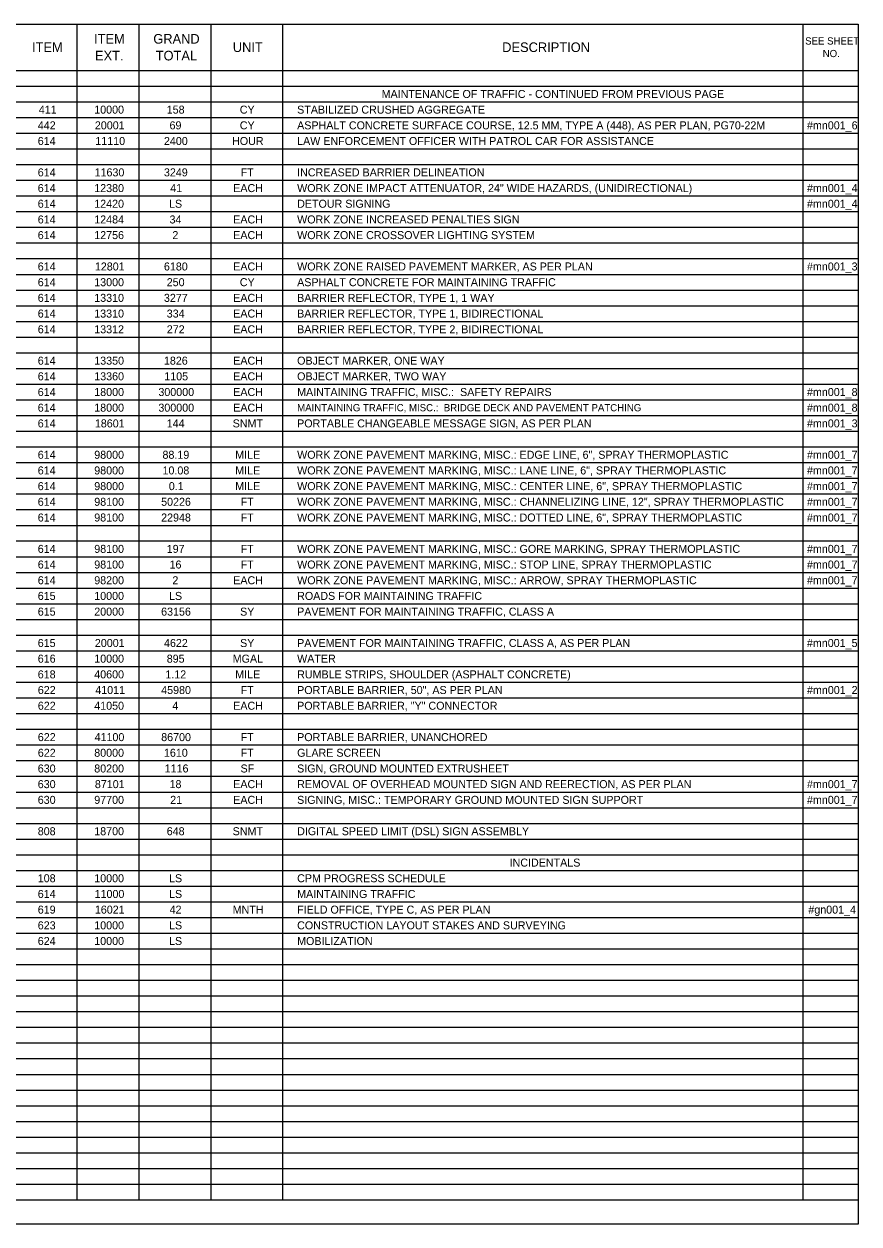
# Model space of a CAD drawing. Extents: x -542 to 295, y -281 to 32.
# Drawn here: x -400.45 to -385.84, y -160.59 to -139.59 of the extents above; entities that cross this region are included whole.
import ezdxf

# ---------------------------------------------------------------- set-up
doc = ezdxf.new("R2010")
doc.units = 0
for name, color, linetype in [('SC_Scratch1', 7, 'Continuous'), ('SH_Data', 7, 'Continuous'), ('SH_Text', 7, 'Continuous')]:
    doc.layers.add(name, color=color, linetype=linetype)

msp = doc.modelspace()

# ---------------------------------------------------------------- linework, layer by layer
at = {"layer": 'SC_Scratch1'}
msp.add_lwpolyline([(-416.359, -139.593), (-385.859, -139.593), (-385.859, -160.593), (-416.359, -160.593)], close=True, dxfattribs=at)
at = {"layer": 'SH_Data'}
for p, q in [((-416.359, -139.593), (-385.859, -139.593)), ((-399.523, -139.593), (-399.523, -160.17)), ((-398.437, -139.593), (-398.437, -160.17)), ((-397.182, -139.593), (-397.182, -160.17)), ((-395.926, -139.593), (-395.926, -160.17)), ((-386.827, -139.593), (-386.827, -160.17)), ((-385.859, -139.593), (-385.859, -160.17)), ((-416.359, -140.405), (-385.859, -140.405)), ((-416.359, -140.68), (-385.859, -140.68)), ((-416.359, -140.954), (-385.859, -140.954)), ((-416.359, -141.229), (-385.859, -141.229)), ((-416.359, -141.503), (-385.859, -141.503)), ((-416.359, -141.778), (-385.859, -141.778)), ((-416.359, -142.052), (-385.859, -142.052)), ((-416.359, -142.327), (-385.859, -142.327)), ((-416.359, -142.601), (-385.859, -142.601)), ((-416.359, -142.876), (-385.859, -142.876)), ((-416.359, -143.15), (-385.859, -143.15)), ((-416.359, -143.425), (-385.859, -143.425)), ((-416.359, -143.699), (-385.859, -143.699)), ((-416.359, -143.974), (-385.859, -143.974)), ((-416.359, -144.248), (-385.859, -144.248)), ((-416.359, -144.523), (-385.859, -144.523)), ((-416.359, -144.797), (-385.859, -144.797)), ((-416.359, -145.072), (-385.859, -145.072)), ((-416.359, -145.346), (-385.859, -145.346)), ((-416.359, -145.621), (-385.859, -145.621)), ((-416.359, -145.895), (-385.859, -145.895)), ((-416.359, -146.17), (-385.859, -146.17)), ((-416.359, -146.444), (-385.859, -146.444)), ((-416.359, -146.719), (-385.859, -146.719)), ((-416.359, -146.993), (-385.859, -146.993)), ((-416.359, -147.268), (-385.859, -147.268)), ((-416.359, -147.542), (-385.859, -147.542)), ((-416.359, -147.817), (-385.859, -147.817)), ((-416.359, -148.091), (-385.859, -148.091)), ((-416.359, -148.366), (-385.859, -148.366)), ((-416.359, -148.64), (-385.859, -148.64)), ((-416.359, -148.915), (-385.859, -148.915)), ((-416.359, -149.189), (-385.859, -149.189)), ((-416.359, -149.464), (-385.859, -149.464)), ((-416.359, -149.738), (-385.859, -149.738)), ((-416.359, -150.013), (-385.859, -150.013)), ((-416.359, -150.287), (-385.859, -150.287)), ((-416.359, -150.562), (-385.859, -150.562)), ((-416.359, -150.836), (-385.859, -150.836)), ((-416.359, -151.111), (-385.859, -151.111)), ((-416.359, -151.385), (-385.859, -151.385)), ((-416.359, -151.66), (-385.859, -151.66)), ((-416.359, -151.935), (-385.859, -151.935)), ((-416.359, -152.209), (-385.859, -152.209)), ((-416.359, -152.484), (-385.859, -152.484)), ((-416.359, -152.758), (-385.859, -152.758)), ((-416.359, -153.033), (-385.859, -153.033)), ((-416.359, -153.307), (-385.859, -153.307)), ((-416.359, -153.582), (-385.859, -153.582)), ((-416.359, -153.856), (-385.859, -153.856)), ((-416.359, -154.131), (-385.859, -154.131)), ((-416.359, -154.405), (-385.859, -154.405)), ((-416.359, -154.68), (-385.859, -154.68)), ((-416.359, -154.68), (-385.859, -154.68)), ((-416.359, -154.954), (-385.859, -154.954)), ((-416.359, -155.229), (-385.859, -155.229)), ((-416.359, -155.503), (-385.859, -155.503)), ((-416.359, -155.778), (-385.859, -155.778)), ((-416.359, -156.052), (-385.859, -156.052)), ((-416.359, -156.327), (-385.859, -156.327)), ((-416.359, -156.601), (-385.859, -156.601)), ((-416.359, -156.876), (-385.859, -156.876)), ((-416.359, -157.15), (-385.859, -157.15)), ((-416.359, -157.425), (-385.859, -157.425)), ((-416.359, -157.699), (-385.859, -157.699)), ((-416.359, -157.974), (-385.859, -157.974)), ((-416.359, -158.248), (-385.859, -158.248)), ((-416.359, -158.523), (-385.859, -158.523)), ((-416.359, -158.797), (-385.859, -158.797)), ((-416.359, -159.072), (-385.859, -159.072)), ((-416.359, -159.346), (-385.859, -159.346)), ((-416.359, -159.621), (-385.859, -159.621)), ((-416.359, -159.895), (-385.859, -159.895)), ((-416.359, -160.17), (-385.859, -160.17))]:
    msp.add_line(p, q, dxfattribs=at)

# ---------------------------------------------------------------- texts
at = {"layer": 'SH_Text'}
for s, height, p in [('ITEM', 0.168, (-399.222, -139.936)), ('GRAND ', 0.168, (-398.186, -139.936)), ('SEE SHEET ', 0.126, (-386.784, -139.952)), ('ITEM', 0.168, (-400.307, -140.083)), ('EXT.', 0.168, (-399.205, -140.23)), ('TOTAL', 0.168, (-398.144, -140.23)), ('UNIT', 0.168, (-396.795, -140.083)), ('DESCRIPTION', 0.168, (-392.083, -140.083)), ('NO.', 0.126, (-386.477, -140.172)), ('MAINTENANCE OF TRAFFIC - CONTINUED FROM PREVIOUS PAGE', 0.14, (-394.192, -140.887)), ('411', 0.14, (-400.189, -141.161)), ('10000', 0.14, (-399.219, -141.161)), ('158', 0.14, (-397.951, -141.161)), ('CY', 0.14, (-396.673, -141.161)), ('STABILIZED CRUSHED AGGREGATE', 0.14, (-395.67, -141.161)), ('442', 0.14, (-400.206, -141.436)), ('20001', 0.14, (-399.208, -141.436)), ('69', 0.14, (-397.902, -141.436)), ('CY', 0.14, (-396.673, -141.436)), ('ASPHALT CONCRETE SURFACE COURSE, 12.5 MM, TYPE A (448), AS PER PLAN, PG70-22M', 0.14, (-395.67, -141.436)), ('#mn001_6', 0.14, (-386.752, -141.436)), ('614', 0.14, (-400.207, -141.71)), ('11110', 0.14, (-399.2, -141.71)), ('2400', 0.14, (-398, -141.71)), ('HOUR', 0.14, (-396.808, -141.71)), ('LAW ENFORCEMENT OFFICER WITH PATROL CAR FOR ASSISTANCE', 0.14, (-395.67, -141.71)), ('614', 0.14, (-400.207, -142.259)), ('11630', 0.14, (-399.213, -142.259)), ('3249', 0.14, (-398, -142.259)), ('FT', 0.14, (-396.658, -142.259)), ('INCREASED BARRIER DELINEATION', 0.14, (-395.67, -142.259)), ('614', 0.14, (-400.207, -142.534)), ('12380', 0.14, (-399.219, -142.534)), ('41', 0.14, (-397.89, -142.534)), ('EACH', 0.14, (-396.788, -142.534)), ('WORK ZONE IMPACT ATTENUATOR, 24" WIDE HAZARDS, (UNIDIRECTIONAL)', 0.14, (-395.67, -142.534)), ('#mn001_4', 0.14, (-386.752, -142.534)), ('614', 0.14, (-400.207, -142.808)), ('12420', 0.14, (-399.219, -142.808)), ('LS', 0.14, (-397.911, -142.808)), ('DETOUR SIGNING', 0.14, (-395.67, -142.808)), ('#mn001_4', 0.14, (-386.752, -142.808)), ('614', 0.14, (-400.207, -143.083)), ('12484', 0.14, (-399.219, -143.083)), ('34', 0.14, (-397.902, -143.083)), ('EACH', 0.14, (-396.788, -143.083)), ('WORK ZONE INCREASED PENALTIES SIGN', 0.14, (-395.67, -143.083)), ('614', 0.14, (-400.207, -143.357)), ('12756', 0.14, (-399.219, -143.357)), ('2', 0.14, (-397.852, -143.357)), ('EACH', 0.14, (-396.788, -143.357)), ('WORK ZONE CROSSOVER LIGHTING SYSTEM', 0.14, (-395.67, -143.357)), ('614', 0.14, (-400.207, -143.906)), ('12801', 0.14, (-399.208, -143.906)), ('6180', 0.14, (-398, -143.906)), ('EACH', 0.14, (-396.788, -143.906)), ('WORK ZONE RAISED PAVEMENT MARKER, AS PER PLAN', 0.14, (-395.67, -143.906)), ('#mn001_3', 0.14, (-386.752, -143.906)), ('614', 0.14, (-400.207, -144.181)), ('13000', 0.14, (-399.219, -144.181)), ('250', 0.14, (-397.951, -144.181)), ('CY', 0.14, (-396.673, -144.181)), ('ASPHALT CONCRETE FOR MAINTAINING TRAFFIC', 0.14, (-395.67, -144.181)), ('614', 0.14, (-400.207, -144.455)), ('13310', 0.14, (-399.219, -144.455)), ('3277', 0.14, (-398, -144.455)), ('EACH', 0.14, (-396.788, -144.455)), ('BARRIER REFLECTOR, TYPE 1, 1 WAY', 0.14, (-395.67, -144.455)), ('614', 0.14, (-400.207, -144.73)), ('13310', 0.14, (-399.219, -144.73)), ('334', 0.14, (-397.951, -144.73)), ('EACH', 0.14, (-396.788, -144.73)), ('BARRIER REFLECTOR, TYPE 1, BIDIRECTIONAL', 0.14, (-395.67, -144.73)), ('614', 0.14, (-400.207, -145.005)), ('13312', 0.14, (-399.219, -145.005)), ('272', 0.14, (-397.95, -145.005)), ('EACH', 0.14, (-396.788, -145.005)), ('BARRIER REFLECTOR, TYPE 2, BIDIRECTIONAL', 0.14, (-395.67, -145.005)), ('614', 0.14, (-400.207, -145.554)), ('13350', 0.14, (-399.219, -145.554)), ('1826', 0.14, (-398, -145.554)), ('EACH', 0.14, (-396.788, -145.554)), ('OBJECT MARKER, ONE WAY', 0.14, (-395.67, -145.554)), ('614', 0.14, (-400.207, -145.828)), ('13360', 0.14, (-399.219, -145.828)), ('1105', 0.14, (-397.994, -145.828)), ('EACH', 0.14, (-396.788, -145.828)), ('OBJECT MARKER, TWO WAY', 0.14, (-395.67, -145.828)), ('614', 0.14, (-400.207, -146.103)), ('18000', 0.14, (-399.219, -146.103)), ('300000', 0.14, (-398.097, -146.103)), ('EACH', 0.14, (-396.788, -146.103)), ('MAINTAINING TRAFFIC, MISC.:  SAFETY REPAIRS', 0.14, (-395.67, -146.103)), ('#mn001_8', 0.14, (-386.752, -146.103)), ('614', 0.14, (-400.207, -146.377)), ('18000', 0.14, (-399.219, -146.377)), ('300000', 0.14, (-398.097, -146.377)), ('EACH', 0.14, (-396.788, -146.377)), ('MAINTAINING TRAFFIC, MISC.:  BRIDGE DECK AND PAVEMENT PATCHING', 0.126, (-395.67, -146.37)), ('#mn001_8', 0.14, (-386.752, -146.377)), ('614', 0.14, (-400.207, -146.652)), ('18601', 0.14, (-399.208, -146.652)), ('144', 0.14, (-397.951, -146.652)), ('SNMT', 0.14, (-396.798, -146.652)), ('PORTABLE CHANGEABLE MESSAGE SIGN, AS PER PLAN', 0.14, (-395.67, -146.652)), ('#mn001_3', 0.14, (-386.752, -146.652)), ('614', 0.14, (-400.207, -147.201)), ('98000', 0.14, (-399.219, -147.201)), ('88.19', 0.14, (-398.025, -147.201)), ('MILE', 0.14, (-396.753, -147.201)), ('WORK ZONE PAVEMENT MARKING, MISC.: EDGE LINE, 6", SPRAY THERMOPLASTIC', 0.14, (-395.67, -147.201)), ('#mn001_7', 0.14, (-386.752, -147.201)), ('614', 0.14, (-400.207, -147.475)), ('98000', 0.14, (-399.219, -147.475)), ('10.08', 0.14, (-398.025, -147.475)), ('MILE', 0.14, (-396.753, -147.475)), ('WORK ZONE PAVEMENT MARKING, MISC.: LANE LINE, 6", SPRAY THERMOPLASTIC', 0.14, (-395.67, -147.475)), ('#mn001_7', 0.14, (-386.752, -147.475)), ('614', 0.14, (-400.207, -147.75)), ('98000', 0.14, (-399.219, -147.75)), ('0.1', 0.14, (-397.915, -147.75)), ('MILE', 0.14, (-396.753, -147.75)), ('WORK ZONE PAVEMENT MARKING, MISC.: CENTER LINE, 6", SPRAY THERMOPLASTIC', 0.14, (-395.67, -147.75)), ('#mn001_7', 0.14, (-386.752, -147.75)), ('614', 0.14, (-400.207, -148.024)), ('98100', 0.14, (-399.219, -148.024)), ('50226', 0.14, (-398.049, -148.024)), ('FT', 0.14, (-396.658, -148.024)), ('WORK ZONE PAVEMENT MARKING, MISC.: CHANNELIZING LINE, 12", SPRAY THERMOPLASTIC', 0.14, (-395.67, -148.024)), ('#mn001_7', 0.14, (-386.752, -148.024)), ('614', 0.14, (-400.207, -148.299)), ('98100', 0.14, (-399.219, -148.299)), ('22948', 0.14, (-398.049, -148.299)), ('FT', 0.14, (-396.658, -148.299)), ('WORK ZONE PAVEMENT MARKING, MISC.: DOTTED LINE, 6", SPRAY THERMOPLASTIC', 0.14, (-395.67, -148.299)), ('#mn001_7', 0.14, (-386.752, -148.299)), ('614', 0.14, (-400.207, -148.848)), ('98100', 0.14, (-399.219, -148.848)), ('197', 0.14, (-397.951, -148.848)), ('FT', 0.14, (-396.658, -148.848)), ('WORK ZONE PAVEMENT MARKING, MISC.: GORE MARKING, SPRAY THERMOPLASTIC', 0.14, (-395.67, -148.848)), ('#mn001_7', 0.14, (-386.752, -148.848)), ('614', 0.14, (-400.207, -149.122)), ('98100', 0.14, (-399.219, -149.122)), ('16', 0.14, (-397.902, -149.122)), ('FT', 0.14, (-396.658, -149.122)), ('WORK ZONE PAVEMENT MARKING, MISC.: STOP LINE, SPRAY THERMOPLASTIC', 0.14, (-395.67, -149.122)), ('#mn001_7', 0.14, (-386.752, -149.122)), ('614', 0.14, (-400.207, -149.397)), ('98200', 0.14, (-399.219, -149.397)), ('2', 0.14, (-397.852, -149.397)), ('EACH', 0.14, (-396.788, -149.397)), ('WORK ZONE PAVEMENT MARKING, MISC.: ARROW, SPRAY THERMOPLASTIC', 0.14, (-395.67, -149.397)), ('#mn001_7', 0.14, (-386.752, -149.397)), ('615', 0.14, (-400.207, -149.671)), ('10000', 0.14, (-399.219, -149.671)), ('LS', 0.14, (-397.911, -149.671)), ('ROADS FOR MAINTAINING TRAFFIC', 0.14, (-395.67, -149.671)), ('615', 0.14, (-400.207, -149.946)), ('20000', 0.14, (-399.219, -149.946)), ('63156', 0.14, (-398.049, -149.946)), ('SY', 0.14, (-396.668, -149.946)), ('PAVEMENT FOR MAINTAINING TRAFFIC, CLASS A', 0.14, (-395.67, -149.946)), ('615', 0.14, (-400.207, -150.495)), ('20001', 0.14, (-399.208, -150.495)), ('4622', 0.14, (-397.999, -150.495)), ('SY', 0.14, (-396.668, -150.495)), ('PAVEMENT FOR MAINTAINING TRAFFIC, CLASS A, AS PER PLAN', 0.14, (-395.67, -150.495)), ('#mn001_5', 0.14, (-386.753, -150.495)), ('616', 0.14, (-400.207, -150.769)), ('10000', 0.14, (-399.219, -150.769)), ('895', 0.14, (-397.951, -150.769)), ('MGAL', 0.14, (-396.797, -150.769)), ('WATER', 0.14, (-395.67, -150.769)), ('618', 0.14, (-400.207, -151.044)), ('40600', 0.14, (-399.219, -151.044)), ('1.12', 0.14, (-397.975, -151.044)), ('MILE', 0.14, (-396.753, -151.044)), ('RUMBLE STRIPS, SHOULDER (ASPHALT CONCRETE)', 0.14, (-395.67, -151.044)), ('622', 0.14, (-400.206, -151.318)), ('41011', 0.14, (-399.201, -151.318)), ('45980', 0.14, (-398.048, -151.318)), ('FT', 0.14, (-396.658, -151.318)), ('PORTABLE BARRIER, 50", AS PER PLAN', 0.14, (-395.67, -151.318)), ('#mn001_2', 0.14, (-386.752, -151.318)), ('622', 0.14, (-400.206, -151.593)), ('41050', 0.14, (-399.219, -151.593)), ('4', 0.14, (-397.853, -151.593)), ('EACH', 0.14, (-396.788, -151.593)), ('PORTABLE BARRIER, "Y" CONNECTOR', 0.14, (-395.67, -151.593)), ('622', 0.14, (-400.206, -152.142)), ('41100', 0.14, (-399.213, -152.142)), ('86700', 0.14, (-398.048, -152.142)), ('FT', 0.14, (-396.658, -152.142)), ('PORTABLE BARRIER, UNANCHORED', 0.14, (-395.67, -152.142)), ('622', 0.14, (-400.206, -152.416)), ('80000', 0.14, (-399.219, -152.416)), ('1610', 0.14, (-398, -152.416)), ('FT', 0.14, (-396.658, -152.416)), ('GLARE SCREEN', 0.14, (-395.67, -152.416)), ('630', 0.14, (-400.207, -152.691)), ('80200', 0.14, (-399.219, -152.691)), ('1116', 0.14, (-397.987, -152.691)), ('SF', 0.14, (-396.66, -152.691)), ('SIGN, GROUND MOUNTED EXTRUSHEET', 0.14, (-395.67, -152.691)), ('630', 0.14, (-400.207, -152.965)), ('87101', 0.14, (-399.208, -152.965)), ('18', 0.14, (-397.902, -152.965)), ('EACH', 0.14, (-396.788, -152.965)), ('REMOVAL OF OVERHEAD MOUNTED SIGN AND REERECTION, AS PER PLAN', 0.14, (-395.67, -152.965)), ('#mn001_7', 0.14, (-386.752, -152.965)), ('630', 0.14, (-400.207, -153.24)), ('97700', 0.14, (-399.219, -153.24)), ('21', 0.14, (-397.89, -153.24)), ('EACH', 0.14, (-396.788, -153.24)), ('SIGNING, MISC.: TEMPORARY GROUND MOUNTED SIGN SUPPORT', 0.14, (-395.67, -153.24)), ('#mn001_7', 0.14, (-386.752, -153.24)), ('808', 0.14, (-400.207, -153.789)), ('18700', 0.14, (-399.219, -153.789)), ('648', 0.14, (-397.951, -153.789)), ('SNMT', 0.14, (-396.798, -153.789)), ('DIGITAL SPEED LIMIT (DSL) SIGN ASSEMBLY', 0.14, (-395.67, -153.789)), ('INCIDENTALS', 0.14, (-391.954, -154.338)), ('108', 0.14, (-400.207, -154.612)), ('10000', 0.14, (-399.219, -154.612)), ('LS', 0.14, (-397.911, -154.612)), ('CPM PROGRESS SCHEDULE', 0.14, (-395.67, -154.612)), ('614', 0.14, (-400.207, -154.887)), ('11000', 0.14, (-399.213, -154.887)), ('LS', 0.14, (-397.911, -154.887)), ('MAINTAINING TRAFFIC', 0.14, (-395.67, -154.887)), ('619', 0.14, (-400.207, -155.161)), ('16021', 0.14, (-399.208, -155.161)), ('42', 0.14, (-397.901, -155.161)), ('MNTH', 0.14, (-396.798, -155.161)), ('FIELD OFFICE, TYPE C, AS PER PLAN', 0.14, (-395.67, -155.161)), ('#gn001_4', 0.14, (-386.728, -155.161)), ('623', 0.14, (-400.207, -155.436)), ('10000', 0.14, (-399.219, -155.436)), ('LS', 0.14, (-397.911, -155.436)), ('CONSTRUCTION LAYOUT STAKES AND SURVEYING', 0.14, (-395.67, -155.436)), ('624', 0.14, (-400.207, -155.71)), ('10000', 0.14, (-399.219, -155.71)), ('LS', 0.14, (-397.911, -155.71)), ('MOBILIZATION', 0.14, (-395.67, -155.71))]:
    msp.add_text(s, height=height, dxfattribs=at).set_placement(p)

doc.saveas('drawing.dxf')
